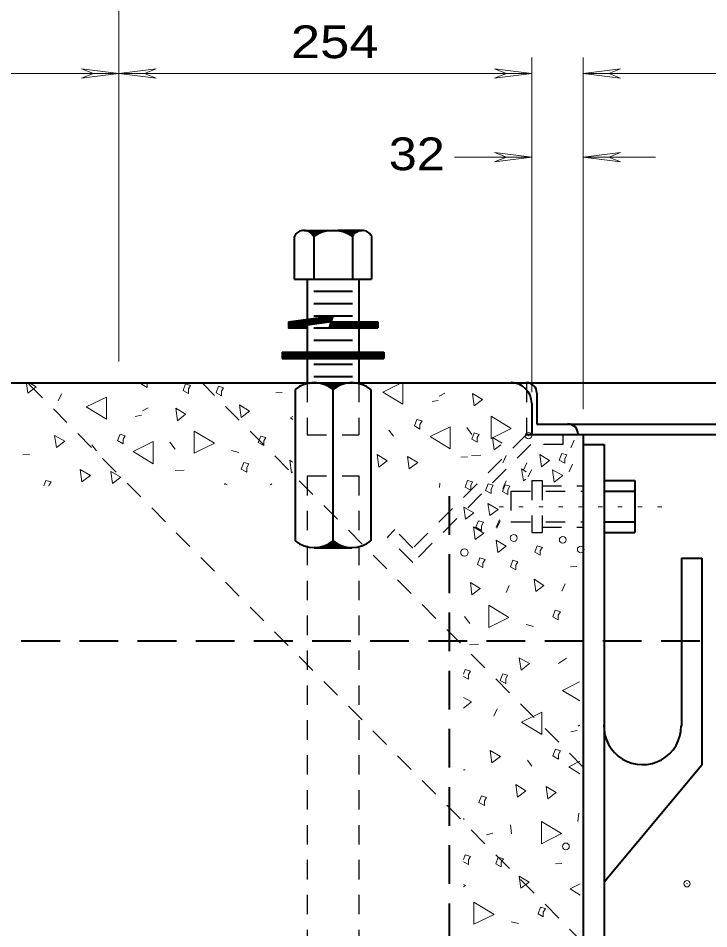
# Model space of a CAD drawing. Extents: x 312583 to 312854, y 144419 to 144597.
# Drawn here: x 312704.63 to 312720.66, y 144459.67 to 144480.8 of the extents above; entities that cross this region are included whole.
import ezdxf

# ---------------------------------------------------------------- set-up
doc = ezdxf.new("R2010")
doc.units = 0
doc.header["$LTSCALE"] = 0.3
doc.header["$PDMODE"] = 32
doc.header["$PDSIZE"] = 0.15
for name, pattern in [('DOTTED', [1.5, 0.3, -1.2]), ('MEDIUM_DASHED', [4.5, 3, -1.5]), ('SHORT_DASHED', [2.7, 1.5, -1.2])]:
    doc.linetypes.add(name, pattern=pattern)
doc.layers.add('1', color=7, linetype='Continuous', lineweight=13)

msp = doc.modelspace()

# ---------------------------------------------------------------- linework, layer by layer
at = {"layer": '1'}
for p, q in [((312706.9719, 144472.8402), (312706.9719, 144481.6415)), ((312716.5553, 144472.1272), (312716.5553, 144479.8935)), ((312717.7513, 144471.7285), (312717.7513, 144479.8935)), ((312706.1056, 144479.6252), (312706.3816, 144479.5179)), ((312706.9719, 144479.5179), (312706.1056, 144479.6252)), ((312706.1056, 144479.4105), (312706.3816, 144479.5179)), ((312706.9719, 144479.5179), (312706.1056, 144479.4105)), ((312706.9719, 144479.5179), (312707.8383, 144479.6252)), ((312706.9719, 144479.5179), (312707.8383, 144479.4105)), ((312707.8383, 144479.6252), (312707.5623, 144479.5179)), ((312707.8383, 144479.4105), (312707.5623, 144479.5179)), ((312715.6889, 144479.6252), (312715.9649, 144479.5179)), ((312716.5553, 144479.5179), (312715.6889, 144479.6252)), ((312715.6889, 144479.4105), (312715.9649, 144479.5179)), ((312716.5553, 144479.5179), (312715.6889, 144479.4105)), ((312717.7513, 144479.5179), (312718.6176, 144479.6252)), ((312717.7513, 144479.5179), (312726.3763, 144479.5179)), ((312717.7513, 144479.5179), (312718.6176, 144479.4105)), ((312718.6176, 144479.6252), (312718.3416, 144479.5179)), ((312718.6176, 144479.4105), (312718.3416, 144479.5179)), ((312714.7613, 144477.5782), (312716.5553, 144477.5782)), ((312715.6889, 144477.6855), (312715.9649, 144477.5782)), ((312716.5553, 144477.5782), (312715.6889, 144477.6855)), ((312715.6889, 144477.4709), (312715.9649, 144477.5782)), ((312716.5553, 144477.5782), (312715.6889, 144477.4709)), ((312717.7513, 144477.5782), (312718.6176, 144477.6855)), ((312717.7513, 144477.5782), (312719.4303, 144477.5782)), ((312717.7513, 144477.5782), (312718.6176, 144477.4709)), ((312718.6176, 144477.6855), (312718.3416, 144477.5782)), ((312718.6176, 144477.4709), (312718.3416, 144477.5782)), ((312704.8253, 144472.3265), (312704.8559, 144472.1042)), ((312707.4703, 144472.3265), (312707.6236, 144472.2345)), ((312707.6236, 144472.2345), (312707.6236, 144472.3265)), ((312712.4843, 144472.3419), (312712.4766, 144472.3265)), ((312713.5653, 144471.8435), (312713.5653, 144472.3419)), ((312705.6379, 144472.0889), (312705.5613, 144471.9202)), ((312710.6136, 144472.1119), (312710.7593, 144472.1195)), ((312714.4086, 144472.0352), (312714.5389, 144472.1042)), ((312714.2399, 144471.9049), (312714.3856, 144471.9279)), ((312707.5163, 144471.6902), (312707.6466, 144471.7592)), ((312707.3476, 144471.5599), (312707.4933, 144471.5905)), ((312713.2356, 144471.2455), (312713.3429, 144471.1075)), ((312715.0449, 144471.3069), (312715.1676, 144471.1459)), ((312717.5366, 144471.0079), (312717.4599, 144470.8315)), ((312706.3433, 144470.9005), (312706.4506, 144470.7625)), ((312708.1526, 144470.9619), (312708.2753, 144470.8009)), ((312715.6813, 144470.7855), (312715.8346, 144470.9005)), ((312704.7409, 144470.6705), (312704.8943, 144470.6782)), ((312709.5863, 144470.7702), (312709.7549, 144470.7242)), ((312714.9069, 144470.6169), (312715.0603, 144470.6245)), ((312715.1599, 144470.6552), (312715.3746, 144470.6629)), ((312715.9573, 144470.6552), (312715.8806, 144470.4865)), ((312716.4403, 144470.4865), (312716.3636, 144470.3179)), ((312717.4983, 144470.4559), (312717.4216, 144470.2795)), ((312708.2753, 144470.3102), (312708.4823, 144470.3179)), ((312710.9739, 144470.2565), (312711.0046, 144470.2795)), ((312716.5476, 144470.3255), (312716.4709, 144470.1569)), ((312705.3543, 144469.9499), (312705.3466, 144469.9575)), ((312710.5216, 144469.9959), (312710.4909, 144469.9729)), ((312714.4163, 144469.9115), (312714.4239, 144470.0112)), ((312715.9573, 144470.0649), (312715.8806, 144469.8885)), ((312716.3636, 144470.0649), (312716.4173, 144470.1032)), ((312715.8039, 144469.1602), (312715.7273, 144468.9915)), ((312715.8193, 144469.1372), (312715.7426, 144468.9685)), ((312717.4523, 144468.0715), (312717.5979, 144468.0792)), ((312716.0339, 144467.6422), (312715.9573, 144467.4735)), ((312717.3296, 144467.6805), (312717.2529, 144467.5042)), ((312714.9913, 144466.9215), (312715.1139, 144466.7605)), ((312716.4249, 144466.7299), (312716.5936, 144466.6839)), ((312715.1063, 144466.2622), (312715.3209, 144466.2775)), ((312717.3603, 144465.9555), (312717.1763, 144465.8252)), ((312715.7503, 144464.7749), (312715.6736, 144464.6062)), ((312717.4599, 144464.2459), (312717.6056, 144464.2765)), ((312717.6286, 144464.3762), (312717.6746, 144464.3992)), ((312716.4556, 144463.5865), (312716.5553, 144463.4485)), ((312714.9683, 144463.3642), (312715.0066, 144463.3642)), ((312717.6209, 144462.1605), (312717.6439, 144462.3522)), ((312714.9683, 144462.2295), (312714.9836, 144462.2065)), ((312716.0646, 144462.0839), (312716.0876, 144461.8769)), ((312715.5049, 144461.8539), (312715.6506, 144461.8922)), ((312717.1073, 144461.1792), (312717.2529, 144461.1869)), ((312716.0799, 144459.8375), (312716.2486, 144459.7992))]:
    msp.add_line(p, q, dxfattribs=at)
at = {"layer": '1', "lineweight": 40}
for p, q in [((312711.2729, 144475.8762), (312712.6146, 144475.8762)), ((312711.0429, 144475.7382), (312711.0429, 144474.7492)), ((312711.4953, 144475.7382), (312711.4953, 144474.7492)), ((312712.3923, 144475.7382), (312712.3923, 144474.7492)), ((312712.8369, 144475.7382), (312712.8369, 144474.7492)), ((312711.0429, 144474.7492), (312712.8369, 144474.7492)), ((312711.3419, 144474.7492), (312711.3419, 144472.3419)), ((312712.5379, 144474.7492), (312712.5379, 144472.3419)), ((312711.4953, 144474.4655), (312712.3923, 144474.4655)), ((312711.4953, 144474.1819), (312712.3923, 144474.1819)), ((312710.9049, 144473.7602), (312710.9049, 144473.6145)), ((312711.4953, 144473.8982), (312712.3923, 144473.8982)), ((312711.9016, 144473.7602), (312712.9826, 144473.7602)), ((312712.9826, 144473.7602), (312712.9826, 144473.6145)), ((312711.4953, 144473.6145), (312712.3923, 144473.6145)), ((312711.8556, 144473.6145), (312712.9826, 144473.6145)), ((312711.4953, 144473.3309), (312712.3923, 144473.3309)), ((312710.7593, 144473.0549), (312713.1206, 144473.0549)), ((312710.7593, 144473.0549), (312710.7593, 144472.9092)), ((312710.7593, 144473.0165), (312713.1206, 144473.0165)), ((312710.7593, 144472.9782), (312713.1206, 144472.9782)), ((312710.7593, 144472.9399), (312713.1206, 144472.9399)), ((312710.7593, 144472.9092), (312713.1206, 144472.9092)), ((312713.1206, 144473.0549), (312713.1206, 144472.9092)), ((312711.4953, 144472.7712), (312712.3923, 144472.7712)), ((312711.4953, 144472.4875), (312712.3923, 144472.4875)), ((312697.8639, 144472.3419), (312716.0723, 144472.3419)), ((312711.3419, 144472.3419), (312712.5379, 144472.3419)), ((312711.5029, 144472.3419), (312712.3769, 144472.3419)), ((312711.9399, 144472.3419), (312711.9399, 144468.5162)), ((312716.0723, 144472.3419), (312740.2759, 144472.3419)), ((312711.0659, 144472.1885), (312711.0659, 144468.6772)), ((312712.8216, 144472.1885), (312712.8216, 144468.6772)), ((312716.6703, 144472.1042), (312716.6703, 144471.3835)), ((312716.5553, 144471.8665), (312716.5553, 144471.1459)), ((312716.6703, 144471.3835), (312735.9596, 144471.3835)), ((312716.4326, 144471.1459), (312736.1973, 144471.1459)), ((312717.7513, 144471.1459), (312717.7513, 144429.2169)), ((312717.7513, 144470.9082), (312718.2343, 144470.9082)), ((312718.2343, 144470.9082), (312718.2343, 144440.2415)), ((312718.2343, 144470.0725), (312718.9473, 144470.0725)), ((312718.9473, 144470.0725), (312718.9473, 144468.8689)), ((312718.2343, 144469.8272), (312718.9473, 144469.8272)), ((312718.2343, 144469.1142), (312718.9473, 144469.1142)), ((312718.2343, 144468.8689), (312718.9473, 144468.8689)), ((312711.5029, 144468.5162), (312712.3769, 144468.5162)), ((312720.0283, 144468.2709), (312720.0283, 144464.3762)), ((312720.0283, 144468.2709), (312720.5036, 144468.2709)), ((312720.5036, 144468.2709), (312720.5036, 144463.4792)), ((312718.2343, 144460.7652), (312720.5036, 144463.4792))]:
    msp.add_line(p, q, dxfattribs=at)
at = {"layer": '1', "linetype": 'SHORT_DASHED', "lineweight": 25}
for p, q in [((312717.7513, 144459.3469), (312704.8483, 144472.3419)), ((312717.7513, 144463.4255), (312708.9039, 144472.3419)), ((312711.3419, 144472.3419), (312711.3419, 144471.1382)), ((312712.5379, 144472.3419), (312712.5379, 144471.1382)), ((312716.4326, 144472.3419), (312716.4326, 144471.1459)), ((312711.3419, 144471.1382), (312712.5379, 144471.1382)), ((312716.4326, 144471.1459), (312713.7953, 144468.5085)), ((312717.2759, 144471.1459), (312717.2759, 144470.9082)), ((312716.5323, 144470.9082), (312713.7953, 144468.1712)), ((312717.2759, 144470.9082), (312716.5323, 144470.9082)), ((312711.3419, 144470.1799), (312712.5379, 144470.1799)), ((312711.3419, 144470.1799), (312711.3419, 144437.9569)), ((312712.5379, 144470.1799), (312712.5379, 144437.9569)), ((312716.5553, 144470.0725), (312716.5553, 144468.8689)), ((312716.5553, 144470.0725), (312716.7929, 144470.0725)), ((312716.7929, 144470.0725), (312716.7929, 144468.8689)), ((312716.7929, 144469.9499), (312717.7513, 144469.9499)), ((312716.0723, 144469.8272), (312716.0723, 144469.1142)), ((312716.0723, 144469.8272), (312717.7513, 144469.8272)), ((312716.0723, 144469.1142), (312717.7513, 144469.1142)), ((312713.3736, 144468.9379), (312713.2049, 144468.7615)), ((312713.7953, 144468.5085), (312713.3736, 144468.9379)), ((312716.7929, 144468.9915), (312717.7513, 144468.9915)), ((312713.7953, 144468.1712), (312713.2049, 144468.7615)), ((312716.5553, 144468.8689), (312716.7929, 144468.8689))]:
    msp.add_line(p, q, dxfattribs=at)
at = {"layer": '1', "linetype": 'MEDIUM_DASHED', "lineweight": 40}
for p, q in [((312714.6386, 144469.7122), (312714.6386, 144432.0919)), ((312699.3053, 144466.3542), (312738.8346, 144466.3542))]:
    msp.add_line(p, q, dxfattribs=at)
at = {"layer": '1', "linetype": 'DOTTED'}
msp.add_line((312715.7963, 144469.4669), (312719.8059, 144469.4669), dxfattribs=at)
at = {"layer": '1'}
for points in [[(312697.3886, 144479.5179), (312706.9719, 144479.5179), (312716.5553, 144479.5179)], [(312704.8559, 144472.1042), (312705.0476, 144472.2499), (312704.9173, 144472.3265)], [(312713.5346, 144472.3419), (312713.0976, 144472.1272), (312713.5653, 144471.8435)], [(312711.0123, 144471.5599), (312710.9509, 144471.5292), (312711.0123, 144471.4909)], [(312715.8653, 144470.9389), (312715.6429, 144471.0692), (312715.6813, 144470.7855)], [(312711.0046, 144470.5019), (312710.9356, 144470.5479), (312710.9739, 144470.2565)], [(312716.4249, 144470.2795), (312716.3176, 144470.3485), (312716.3636, 144470.0649)], [(312705.3466, 144469.9575), (312705.4003, 144470.0419), (312705.2776, 144470.0725), (312705.2316, 144469.9499)], [(312709.4866, 144469.9729), (312709.4329, 144470.0035), (312709.4329, 144469.9729)], [(312715.0833, 144465.5722), (312715.1293, 144465.6489), (312715.0066, 144465.6872), (312714.9683, 144465.5799)], [(312714.9683, 144465.5262), (312715.0833, 144465.4649), (312715.0833, 144465.5722)], [(312717.6669, 144465.4035), (312717.2683, 144465.2042), (312717.6746, 144464.9589)], [(312714.9683, 144464.7902), (312715.1599, 144464.9359), (312714.9683, 144465.0432)], [(312717.6746, 144463.5635), (312717.4139, 144463.4332), (312717.6746, 144463.2722)], [(312715.0833, 144461.2712), (312715.1293, 144461.3479), (312715.0066, 144461.3862), (312714.9683, 144461.2789)], [(312714.9683, 144461.2252), (312715.0833, 144461.1639), (312715.0833, 144461.2712)], [(312714.9683, 144460.6425), (312715.0143, 144460.6809), (312714.9683, 144460.7039)], [(312717.6823, 144460.7192), (312717.4446, 144460.5965), (312717.6823, 144460.4509)]]:
    msp.add_lwpolyline(points, dxfattribs=at)
at = {"layer": '1', "lineweight": 40}
for points in [[(312711.3266, 144475.8762), (312711.8249, 144475.8762), (312711.7406, 144475.8609), (312711.6869, 144475.8455), (312711.5949, 144475.8072), (312711.4953, 144475.7459), (312711.4646, 144475.7995), (312711.4186, 144475.8302), (312711.3496, 144475.8685), (312711.7866, 144475.8685), (312711.6639, 144475.8455), (312711.5719, 144475.7995), (312711.5029, 144475.7612), (312711.4263, 144475.8302), (312711.3803, 144475.8609), (312711.7329, 144475.8685), (312711.6103, 144475.8302), (312711.5029, 144475.7689), (312711.4033, 144475.8532), (312711.6946, 144475.8609), (312711.4953, 144475.7842), (312711.4186, 144475.8532), (312711.6639, 144475.8532), (312711.4876, 144475.7919), (312711.4416, 144475.8455), (312711.6256, 144475.8532), (312711.4953, 144475.8072), (312711.4569, 144475.8379), (312711.5796, 144475.8379), (312711.5029, 144475.8149), (312711.4799, 144475.8379), (312711.5336, 144475.8302), (312711.5029, 144475.8225)], [(312712.5609, 144475.8762), (312712.0549, 144475.8762), (312712.1393, 144475.8609), (312712.2006, 144475.8455), (312712.2926, 144475.8072), (312712.3923, 144475.7459), (312712.4229, 144475.7995), (312712.4613, 144475.8302), (312712.5379, 144475.8685), (312712.1009, 144475.8685), (312712.2236, 144475.8455), (312712.3156, 144475.7995), (312712.3846, 144475.7612), (312712.4536, 144475.8302), (312712.5073, 144475.8609), (312712.1546, 144475.8685), (312712.2773, 144475.8302), (312712.3846, 144475.7689), (312712.4843, 144475.8532), (312712.1929, 144475.8609), (312712.3923, 144475.7842), (312712.4689, 144475.8532), (312712.2236, 144475.8532), (312712.3923, 144475.7919), (312712.4459, 144475.8455), (312712.2619, 144475.8532), (312712.3923, 144475.8072), (312712.4229, 144475.8379), (312712.3079, 144475.8379), (312712.3846, 144475.8149), (312712.3999, 144475.8379), (312712.3539, 144475.8302), (312712.3846, 144475.8225)], [(312710.9049, 144473.7602), (312711.9399, 144473.8982), (312711.8556, 144473.6145)], [(312711.9016, 144473.7602), (312710.9049, 144473.6145), (312711.3419, 144473.6145)], [(312711.3419, 144473.6145), (312710.9126, 144473.6375), (312710.9203, 144473.7449), (312711.9169, 144473.8752), (312711.8786, 144473.7755), (312711.3343, 144473.6912), (312711.3266, 144473.6375), (312710.9279, 144473.6529), (312710.9356, 144473.7295), (312711.8939, 144473.8599), (312711.8633, 144473.7832), (312711.3113, 144473.6989), (312711.3036, 144473.6529), (312710.9433, 144473.6682), (312710.9433, 144473.7065), (312711.8479, 144473.8369), (312711.8556, 144473.8062), (312711.3189, 144473.7142), (312711.2883, 144473.6989), (312711.1733, 144473.6682), (312710.9663, 144473.6835), (312711.8249, 144473.8215), (312711.1043, 144473.6835)], [(312711.8786, 144473.6375), (312712.9596, 144473.6375), (312712.9596, 144473.7449), (312711.9169, 144473.7372), (312711.8786, 144473.6529), (312712.9443, 144473.6452), (312712.9443, 144473.7219), (312711.9323, 144473.7142), (312711.9093, 144473.6682), (312712.9213, 144473.6759), (312712.9059, 144473.6989), (312712.9059, 144473.7065), (312711.9399, 144473.6989), (312711.9246, 144473.6835), (312712.8983, 144473.6835)], [(312711.6179, 144472.3419), (312712.2696, 144472.3419), (312712.1929, 144472.3265), (312712.1239, 144472.3035), (312712.0549, 144472.2729), (312712.0089, 144472.2499), (312711.9476, 144472.2039), (312711.9399, 144472.1962), (312711.8249, 144472.2805), (312711.7176, 144472.3189), (312711.6486, 144472.3342), (312712.2236, 144472.3342), (312712.1776, 144472.3265), (312712.1239, 144472.3189), (312712.0549, 144472.2959), (312711.9859, 144472.2575), (312711.9629, 144472.2345), (312711.9399, 144472.2115), (312711.8326, 144472.2805), (312711.7176, 144472.3265), (312712.1393, 144472.3265), (312712.0396, 144472.2959), (312711.9399, 144472.2345), (312711.7559, 144472.3189), (312712.0933, 144472.3265), (312711.9399, 144472.2269), (312711.7943, 144472.3112), (312712.0626, 144472.3189), (312711.9476, 144472.2499), (312711.8479, 144472.3035), (312712.0243, 144472.3035), (312711.9399, 144472.2805), (312711.8479, 144472.2959), (312711.9093, 144472.2575), (312711.9246, 144472.3035), (312711.9323, 144472.2422), (312711.9783, 144472.2882), (312712.0013, 144472.2882), (312712.0319, 144472.3035)], [(312711.6179, 144468.5239), (312712.2696, 144468.5239), (312712.1929, 144468.5392), (312712.1239, 144468.5545), (312712.0549, 144468.5852), (312712.0089, 144468.6159), (312711.9476, 144468.6542), (312711.9399, 144468.6619), (312711.8249, 144468.5852), (312711.7176, 144468.5469), (312711.6486, 144468.5315), (312712.2236, 144468.5239), (312712.1776, 144468.5315), (312712.1239, 144468.5469), (312712.0549, 144468.5699), (312711.9859, 144468.6082), (312711.9629, 144468.6312), (312711.9399, 144468.6542), (312711.8326, 144468.5775), (312711.7176, 144468.5392), (312712.1393, 144468.5315), (312712.0396, 144468.5699), (312711.9399, 144468.6312), (312711.7559, 144468.5392), (312712.0933, 144468.5392), (312711.9399, 144468.6389), (312711.7943, 144468.5469), (312712.0626, 144468.5469), (312711.9476, 144468.6082), (312711.8479, 144468.5622), (312712.0243, 144468.5545), (312711.9399, 144468.5852), (312711.8479, 144468.5699), (312711.9093, 144468.6005), (312711.9246, 144468.5622), (312711.9323, 144468.6235), (312711.9783, 144468.5775), (312712.0013, 144468.5699), (312712.0319, 144468.5622)]]:
    msp.add_lwpolyline(points, dxfattribs=at)
at = {"layer": '1'}
for points in [[(312708.5896, 144472.2039), (312708.6356, 144472.2805), (312708.5206, 144472.3189), (312708.4593, 144472.1655), (312708.5896, 144472.0965)], [(312709.3563, 144472.1502), (312709.4023, 144472.2269), (312709.2796, 144472.2652), (312709.2259, 144472.1119), (312709.3563, 144472.0429)], [(312715.2213, 144471.8052), (312715.4129, 144471.9509), (312715.1829, 144472.0965)], [(312706.6806, 144471.4985), (312706.6806, 144472.0122), (312706.2129, 144471.7822)], [(312708.3289, 144471.4602), (312708.5206, 144471.6135), (312708.2906, 144471.7515)], [(312709.8086, 144471.5369), (312710.0003, 144471.6825), (312709.7703, 144471.8282)], [(312713.9563, 144471.3759), (312714.0099, 144471.4602), (312713.8873, 144471.4909), (312713.8336, 144471.3452), (312713.9563, 144471.2685)], [(312715.6123, 144471.5675), (312715.6123, 144471.0462), (312716.0799, 144471.2839)], [(312708.7199, 144471.2225), (312708.7199, 144470.7089), (312709.1876, 144470.9389)], [(312714.6616, 144470.8085), (312714.6616, 144471.3222), (312714.1939, 144471.0922)], [(312705.5229, 144470.8392), (312705.7146, 144470.9849), (312705.4769, 144471.1229)], [(312707.0716, 144471.0309), (312707.1176, 144471.1152), (312707.0026, 144471.1535), (312706.9413, 144471.0002), (312707.0716, 144470.9235)], [(312710.3376, 144470.9925), (312710.3836, 144471.0692), (312710.2686, 144471.1075), (312710.2073, 144470.9542), (312710.3376, 144470.8852)], [(312715.2903, 144471.0692), (312715.3363, 144471.1459), (312715.2213, 144471.1842), (312715.1676, 144471.0309), (312715.2903, 144470.9619)], [(312707.7693, 144470.4635), (312707.7693, 144470.9772), (312707.3016, 144470.7472)], [(312713.0056, 144470.3869), (312713.1973, 144470.5325), (312712.9673, 144470.6782)], [(312713.7109, 144470.3485), (312713.9103, 144470.4942), (312713.6726, 144470.6322)], [(312716.7776, 144470.3945), (312716.9693, 144470.5402), (312716.7393, 144470.6782)], [(312717.3219, 144470.5862), (312717.3679, 144470.6705), (312717.2529, 144470.7012), (312717.1916, 144470.5479), (312717.3219, 144470.4789)], [(312709.9389, 144470.3792), (312709.9849, 144470.4635), (312709.8699, 144470.4942), (312709.8086, 144470.3409), (312709.9389, 144470.2719)], [(312706.1133, 144470.0419), (312706.3126, 144470.1875), (312706.0749, 144470.3332)], [(312706.8263, 144470.0035), (312707.0179, 144470.1492), (312706.7803, 144470.2872)], [(312717.0766, 144470.0342), (312717.2759, 144470.1875), (312717.0383, 144470.3255)], [(312715.1369, 144469.9575), (312715.1829, 144470.0419), (312715.0603, 144470.0725), (312715.0066, 144469.9192), (312715.1369, 144469.8502)], [(312715.6123, 144469.8809), (312715.6583, 144469.9652), (312715.5433, 144469.9959), (312715.4819, 144469.8425), (312715.6123, 144469.7735)], [(312716.0033, 144469.8579), (312716.0493, 144469.9422), (312715.9343, 144469.9729), (312715.8729, 144469.8195), (312716.0033, 144469.7505)], [(312715.5816, 144469.2599), (312715.7733, 144469.4055), (312715.5356, 144469.5435)], [(312715.0143, 144469.1755), (312715.2136, 144469.3212), (312714.9759, 144469.4592)], [(312715.3899, 144469.0222), (312715.4359, 144469.1065), (312715.3209, 144469.1372), (312715.2596, 144468.9915), (312715.3899, 144468.9149)], [(312715.2443, 144468.7079), (312715.4436, 144468.8535), (312715.2059, 144468.9992)], [(312715.7656, 144468.4012), (312715.9573, 144468.5545), (312715.7273, 144468.6925)], [(312716.7469, 144468.4472), (312716.8006, 144468.5239), (312716.6779, 144468.5622), (312716.6243, 144468.4089), (312716.7469, 144468.3399)], [(312715.4206, 144468.1559), (312715.4743, 144468.2402), (312715.3516, 144468.2785), (312715.2979, 144468.1252), (312715.4206, 144468.0562)], [(312716.1873, 144468.1099), (312716.2333, 144468.1865), (312716.1183, 144468.2249), (312716.0646, 144468.0715), (312716.1873, 144468.0025)], [(312715.1676, 144467.4199), (312715.3593, 144467.5655), (312715.1293, 144467.7112)], [(312716.6473, 144467.4965), (312716.8389, 144467.6422), (312716.6089, 144467.7879)], [(312715.5586, 144467.1822), (312715.5586, 144466.6609), (312716.0263, 144466.8985)], [(312717.1686, 144466.9522), (312717.2223, 144467.0289), (312717.0996, 144467.0672), (312717.0459, 144466.9139), (312717.1686, 144466.8449)], [(312716.3099, 144465.6719), (312716.5016, 144465.8252), (312716.2639, 144465.9632)], [(312715.9496, 144465.4725), (312715.9956, 144465.5569), (312715.8806, 144465.5875), (312715.8193, 144465.4342), (312715.9496, 144465.3652)], [(312716.7853, 144464.1845), (312716.7853, 144464.6982), (312716.3176, 144464.4682)], [(312717.1763, 144463.7169), (312717.2223, 144463.8012), (312717.1073, 144463.8395), (312717.0459, 144463.6862), (312717.1763, 144463.6095)], [(312715.6276, 144463.5252), (312715.8269, 144463.6709), (312715.5893, 144463.8089)], [(312716.2256, 144462.7279), (312716.4173, 144462.8735), (312716.1873, 144463.0192)], [(312716.9309, 144462.6895), (312717.1226, 144462.8352), (312716.8926, 144462.9732)], [(312715.4589, 144462.6435), (312715.5049, 144462.7202), (312715.3899, 144462.7585), (312715.3286, 144462.6052), (312715.4589, 144462.5362)], [(312716.7776, 144462.1605), (312716.7776, 144461.6469), (312717.2453, 144461.8845)], [(312715.8423, 144461.2175), (312715.8959, 144461.2942), (312715.7733, 144461.3325), (312715.7196, 144461.1792), (312715.8423, 144461.1102)], [(312716.3023, 144460.6119), (312716.4939, 144460.7575), (312716.2639, 144460.8955)], [(312715.2136, 144460.2899), (312715.2136, 144459.7762), (312715.6813, 144460.0062)], [(312716.8236, 144460.0599), (312716.8773, 144460.1442), (312716.7546, 144460.1749), (312716.7009, 144460.0215), (312716.8236, 144459.9525)]]:
    msp.add_lwpolyline(points, close=True, dxfattribs=at)
for centre, radius in [((312716.1355, 144468.7414), 0.0784), ((312717.274, 144468.6974), 0.0784), ((312714.9917, 144468.4048), 0.0865), ((312717.6919, 144468.475), 0.0784), ((312717.3476, 144461.5847), 0.0784)]:
    msp.add_circle(centre, radius, dxfattribs=at)
at = {"layer": '1', "lineweight": 40}
for centre, radius, start, end in [((312711.2685, 144475.6305), 0.2489, 25.60064, 154.39936), ((312711.9419, 144475.0958), 0.7836, 55.04559, 124.95441), ((312712.6153, 144475.6305), 0.2489, 25.60064, 154.39936), ((312711.5036, 144471.6636), 0.6817, 50.00693, 129.99306), ((312712.3799, 144471.6636), 0.6817, 50.00694, 129.99307), ((312716.0742, 144471.8665), 0.4792, 0, 90), ((312716.4336, 144472.1061), 0.2396, 0, 90), ((312717.3919, 144471.1478), 0.2396, 0, 90), ((312711.5036, 144469.2005), 0.6817, 230.00694, 309.99307), ((312712.3799, 144469.2005), 0.6817, 230.00693, 309.99306), ((312719.1284, 144464.3796), 0.8984, 178.12864, 359.96943)]:
    msp.add_arc(centre, radius, start, end, dxfattribs=at)
at = {"layer": '1'}
for p in [(312716.4786, 144471.1152), (312720.1586, 144460.7192)]:
    msp.add_point(p, dxfattribs=at)

# ---------------------------------------------------------------- texts
for s, width, p in [('254 ', 1.2, (312710.9633, 144479.8752)), ('32 ', 1.15, (312713.2362, 144477.2747))]:
    msp.add_text(s, height=0.76, dxfattribs=dict(at, width=width)).set_placement(p)

doc.saveas('drawing.dxf')
